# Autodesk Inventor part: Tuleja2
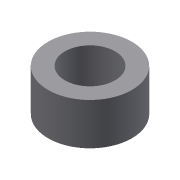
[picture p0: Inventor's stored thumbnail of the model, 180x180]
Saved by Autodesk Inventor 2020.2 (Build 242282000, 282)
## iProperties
Created: 2005-10
Part Number: Tuleja2
Document SubType Name: Modeling
Designer: F.Stasiak
Material: Ogólny
Density: 1 g/cm^3
Appearance: Domyślna
Manager: www.cadconsulting.pl
Company: Fabian Stasiak CAD Consulting
Author: F.Stasiak
Subject: Zbiór ćwiczeń. Autodesk Inventor 2020. Kurs podstawowy
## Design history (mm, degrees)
sketch "Szkic1"
  geometry: C1 r 50 at (0, 0); C2 r 30 at (0, 0); 1 further point
  constraints: 2 centre point, 2 coincident
  dimensions: "d0" = 100 diameter of C1; "d1" = 60 diameter of C2
extrude "Wyciągnięcie proste1" new body sketch "Szkic1" distance "d2" = 50; taper "d3" = 0 deg
node "Bryła1"
node "Korpusy bryłowe"
node "Korpusy powierzchniowe"
